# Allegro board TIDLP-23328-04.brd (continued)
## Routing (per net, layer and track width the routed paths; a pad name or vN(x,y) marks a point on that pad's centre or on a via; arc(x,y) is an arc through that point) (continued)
HUM_DRDYZ: length 27.4
  TOP w0.099: v1(57.78,36.83) 57.84,36.88 57.84,37.43 U6.D2 59.06,37.68 R18.1
  LY4-SIG w0.102: v1(44.47,31.01) 45.34,31.88 45.34,35.56 46.99,37.21 46.99,37.72 v1(47.12,37.85)
  LY8-SIG w0.102: v1(47.12,37.85) 48.26,38.99 53.21,38.99 55.37,36.83 v1(57.78,36.83)
  BOTTOM w0.099: U1.A8 40.64,29.52 41.05,29.93 41.05,30.84 41.52,31.31 44.16,31.31 v1(44.47,31.01)
HUM_SCL: length 25
  TOP w0.099: R20.1 57.74,41.61 57.28,41.15 v1(57.28,40.26) 57.09,40.07 U6.A1
  LY3-SIG w0.102: v2(45.27,27.84) 45.87,27.84 48.9,30.86 48.9,31.37 49.91,32.38 50.29,32.38 51.69,33.78 54.1,33.78 57.28,36.96 v1(57.28,40.26)
  BOTTOM w0.099: U1.F2 43.99,27.12 44.73,27.12 45.27,27.65 v2(45.27,27.84)
HUM_SDA: length 25.2
  TOP w0.099: U6.A2 58.09,39.57 v1(57.91,39.75) 57.91,40.04 R19.1
  LY3-SIG w0.102: v1(57.91,39.75) 58.17,39.5 58.17,36.58 56.26,34.67 56.26,30.99 55.5,30.23 48.75,30.23 v2(45.76,27.23)
  BOTTOM w0.099: v2(45.76,27.23) 45.41,27.23 45.06,26.89 44.26,26.89 U1.F1
LI-ION_BATTERY: length 6.5
  BOTTOM w0.203: U19.4 14.55,22.4 R56.2
  BOTTOM w0.305: v1(11.84,21.81) 11.93,21.72 R56.2 ; C71.2 11.21,22.67 J6.1
  vias: v1(10.31,21.81) v1(10.69,21.17) v1(11.08,21.81) v1(11.46,21.17) v1(15.75,25.13) v1(16.13,24.49) v1(16.52,25.13) v1(16.9,24.49) v1(17.28,25.13)
MSD_CARD_DET: length 34.9
  TOP w0.099: v1(16.76,20.57) 16.76,21.32 R7.1 15.64,22.44 P1.13
  LY8-SIG w0.102: v2(38.5,30.66) 38.5,29.63 37.87,29.01 35.25,29.01 34.44,29.82 34.01,29.82 33.43,29.24 32.71,29.24 32.31,28.83 32.31,25.6 29.57,22.86 24.13,22.86 23.62,22.35 21.59,22.35 20.83,23.11 18.41,23.11 17.91,22.61 17.91,21.72 v1(16.76,20.57)
  BOTTOM w0.099: v2(38.5,30.66) 38.25,30.41 38.25,29.93 38.26,29.93 38.26,29.63 38.25,29.63 38.25,29.6 38.14,29.49 U1.A13
MSD_CLK: length 49
  TOP w0.099: P1.5 v1(2.73,10.22)
  LY4-SIG w0.102: v1(2.73,10.22) 4.48,11.97 16.96,11.97 19,14.01 28.07,14.01 29.67,15.61 34.3,15.61 35.31,16.63 40.48,16.63 41.78,17.93 41.78,19.43 42.04,19.68 42.04,21.34 41.66,21.72 v2(41.66,22.5)
  BOTTOM w0.099: U1.T7 41.66,22.28 v2(41.66,22.5)
MSD_CSZ: length 42.7
  TOP w0.099: P1.2 4.13,23.05 v1(4.57,22.61)
  LY4-SIG w0.102: v1(4.57,22.61) 5.09,22.09 9.2,22.09 10.63,20.66 15.02,20.66 15.51,21.14 18.1,21.14 18.35,20.9 22.97,20.9 24.24,19.64 34.8,19.64 35.95,18.48 40.78,18.48 41.02,18.72 41.02,19.34 v2(41.43,19.75)
  BOTTOM w0.099: v2(41.43,19.75) 41.64,19.96 U1.W6 ; v1(4.57,22.61) 4.57,23.36 R5.1
MSD_DI: length 44
  TOP w0.099: P1.3 v1(3.43,22.61)
  LY4-SIG w0.102: v2(41.38,18.99) 41.38,18.54 41.05,18.21 35.64,18.21 34.69,19.15 23.81,19.15 22.77,20.19 18.16,20.19 17.65,19.68 16,19.68 15.36,20.33 9.53,20.33 8.75,21.12 4.92,21.12 v1(3.43,22.61)
  BOTTOM w0.099: U1.V6 41.92,20.49 41.92,19.53 v2(41.38,18.99)
MSD_DO: length 47.4
  TOP w0.099: v1(4.45,10.41) 4.13,10.1 P1.7
  LY4-SIG w0.102: v2(42.42,21.7) 42.42,20.85 42.29,20.72 42.29,19.41 42.52,19.18 42.52,18.76 42.19,18.43 42.19,17.62 40.42,15.85 35.54,15.85 34.55,14.86 29.85,14.86 28.45,13.45 21.65,13.45 19.78,11.59 5.62,11.59 v1(4.45,10.41)
  BOTTOM w0.099: U1.U6 42.08,21.7 v2(42.42,21.7)
Net_207: length 1.8
  BOTTOM w0.099: v2(40.14,30.54) 40.14,28.76
Net_215: length 2.1
  BOTTOM w0.099: 43.64,25.26 43.92,25.54 44.93,25.54 45.37,25.1 v2(45.48,25.1)
OSC0: length 7.2
  BOTTOM w0.099: U1.E19 34.61,27.26 34.35,27.52 33.95,27.52 33.4,28.07 33.4,28.21 33.39,28.21 33.39,28.6 33.15,28.84 C87.2 32.02,29.21 30.35,29.21 29.55,28.41 Y2.1
P1P8V: length 8.2
  TOP w0.203: U7.A1 22.89,11.43 v1(22.89,10.92)
  TOP w0.254: J5.12 43.2,39.98 v1(43.05,40.13) ; C24.1 v1(23.63,10.93) ; J5.11 43.2,43.2 v1(42.8,42.8)
  BOTTOM w0.203: v1(35.59,9.27) 35.26,8.94 U12.A1
  BOTTOM w0.254: v1(43.05,40.13) 43.05,40.88 C61.1 ; R43.1 35.08,11.26 v1(34.49,11.26) ; v1(42.8,42.8) 42.8,42.18 C56.1 ; v1(35.59,9.27) 35.18,9.68 C75.2
P1P8V_BT: length 6.6
  TOP w0.203: U7.A2 22.12,11.48 v1(21.82,11.18)
  TOP w0.254: C13.1 14.04,9.47 v1(14.18,9.61) ; v1(21.82,11.18) 21.49,11.18 21.18,11.48 C20.1
  BOTTOM w0.203: C15.1 11.24,18.36 v1(10.43,18.36) 10.18,18.12 U4.2
  BOTTOM w0.254: U5.18 v1(14.18,9.61) ; R11.2 v1(7.51,12.92)
P3P3V: length 83.5
  TOP w0.203: v1(56.48,38.7) 56.5,38.68 U6.B1
  TOP w0.254: R7.2 17.92,21.46 v1(18.54,21.46) ; R2.2 v1(20.17,33.17) ; J5.8 v1(44,40.07) ; C47.1 v1(51.68,31.08) ; C42.1 36.12,23.31 v2(36.13,23.3) ; R23.2 43.43,5.05 v1(43.43,5.71) ; R18.2 v1(60.1,38.58) ; C36.1 38.26,25.6 v2(38,25.34) ; R28.2 57.21,21.39 v1(57.34,21.52) ; v2(38.01,23.49) 38.34,23.81 C35.1 38.76,23.64 v2(38.76,23.18) ; C6.1 v1(48.29,31.11) ; C50.1 v1(38.71,17.71) ; C85.2 43.77,26.89 v2(43.14,26.26) 43.39,26.01 C86.1 ; R32.2 v1(36.58,14.57) ; C48.1 v1(53.2,31.08) ; R45.1 v1(26.47,15.84) ; C38.1 v1(46.96,17.57) ; U13.4 v1(33.61,16.45) ; v2(54.22,27.52) 54.56,27.18 C7.1 ; R22.2 45.21,6.83 v1(45.21,7.24) ; v2(40.22,22.65) 40.06,22.49 40.06,22.05 C41.1 ; C45.1 v1(29.56,32.64) ; v2(55.02,23.52) 54.9,23.64 C4.1 ; C40.1 v1(50.26,17.57) ; R25.2 v1(47.19,29.92) ; C33.1 40.66,25.46 40.66,25.66 v2(41.11,26.11) ; C2.1 52.57,28.27 v2(51.82,27.52) ; R26.2 v1(47.32,26.59) ; v1(38.5,36.19) 39.25,36.19 R35.2 ; C44.1 v1(34.32,17.57) ; C49.1 v1(54.75,31.1) ; C5.1 56.34,27 v2(55.82,27.52) ; v1(52.14,33.08) 52.18,33.13 C55.1 ; v1(40.64,35.56) 40.39,35.81 R36.2 ; R17.2 41.4,36.18 v1(41.4,35.56) ; C34.1 39.83,25.61 40.19,25.96 v2(40.19,26.23) ; C39.1 v1(48.61,17.57) ; R3.2 v1(21.19,33.17) ; C28.1 v1(28.09,0.89) ; C12.1 21.46,9.14 v1(20.7,9.14) ; J5.7 44,42.87 v1(44.2,42.67) ; C37.1 v1(45.31,17.57) ; C46.1 v1(50.15,30.82) ; C3.1 53.14,23.8 v2(53.42,23.52) ; R6.2 v1(5.82,8.51) ; C1.1 v1(48.29,19.95) ; C23.1 v1(56.48,38.7) ; R1.2 v1(23.22,33.17) ; C43.1 v1(32.58,17.57) ; R4.2 v1(16.66,28.73) ; R20.2 v1(60.33,41.61) ; R27.2 v1(58.23,34.73) ; R19.2 v1(60.33,40.59) ; R24.2 41.66,3.28 v1(41.66,3.81) ; P1.4 v1(2.73,24.7) ; C8.1 v1(58.42,26.5)
  BOTTOM w0.203: U1.J10 U1.J9 ; U1.J9 U1.H9 ; U1.J9 U1.J8 ; v2(38,25.34) 38.07,25.34 U1.K12 U1.K11 ; U1.H9 40.14,26.11 40.19,26.15 v2(40.19,26.23) 40.15,26.26 U1.G10 ; U1.H9 40.77,25.76 ; U1.F3 v2(43.14,26.26) ; U1.L10 U1.L11 U1.M11 39.14,23.56 v2(38.76,23.18) ; 40.77,25.76 40.64,25.64 U1.J8 ; 40.77,25.76 v2(41.11,26.11) ; U1.J8 U1.K8 U1.K7 v2(41.14,25.31) 41.1,25.26 U1.J8 ; v2(42.17,26.82) 42.21,26.82 42.26,26.76 U1.F4 ; U1.L12 U1.M12 38.29,23.77 v2(38.01,23.49) ; U1.N16 36.61,23.3 v2(36.13,23.3) 36.14,23.29 U1.P17 ; U1.P10 39.93,22.77 40.02,22.67 40.2,22.67 v2(40.22,22.65) ; C19.1 v1(5.09,18.15) 5.13,18.12 U4.15
  BOTTOM w0.254: C25.1 42.4,13.12 v1(42.95,12.57) 43.87,11.65 J3.1 ; C10.1 2.73,23.93 v1(2.73,24.7) ; v1(44,40.07) 44,40.82 C60.1 ; U9.14 v1(52.14,33.08) ; U5.12 19.9,9.69 20.45,9.14 v1(20.7,9.14) 21.48,9.14 C11.1 ; U2.B3 v2(55.02,23.52) ; R37.2 v1(41.4,35.56) ; v1(28.09,0.89) 28.09,2.66 J4.1 ; C22.1 v1(27.95,37.34) 27.95,37.34 J2.3 ; U2.A9 v2(55.82,29.12) ; C57.1 44.2,42.18 v1(44.2,42.67) ; U2.A7 v2(55.82,27.52) ; R5.2 v1(3.67,24.63) ; U2.C7 v2(54.22,27.52) ; U2.E7 v2(51.82,27.52) ; U2.J9 v2(48.62,29.12) ; U2.D3 v2(53.42,23.52)
  vias: v1(26.04,17.86) v1(26.04,17.14) v1(26.8,17.86) v1(26.8,17.14)
P5P0V: length 4.2
  TOP w0.203: 31.78,11.43 31.76,11.44 U14.B3 ; U14.C3 31.5,10.64 31.75,10.64 31.78,10.67 ; U14.A3 31.75,12.44 31.75,12.45
  BOTTOM w0.254: J2.2 26.95,38.24 v1(26.05,37.34) C21.1
  vias: v1(32.13,13.76) v1(32.13,12.99)
P_LDO_V: length 58.8
  TOP w0.099: R44.1 v1(16.53,27.71) ; v1(45.85,7.75) 46.13,7.75 46.59,8.21 R42.2 ; C72.2 v1(25.34,30.58) 24.92,30.15 24.92,29.08 24.54,28.7 U10.24
  LY3-SIG w0.102: v1(16.53,27.71) 21.72,22.52 21.72,19.91 27.49,14.15 30.3,14.15 31.37,13.08 31.37,11.56 35.94,6.99 35.94,6.1 36.58,5.46 37.72,5.46 38.86,4.32 41.15,4.32 44.58,7.75 v1(45.85,7.75)
  BOTTOM w0.099: v1(25.34,30.58) 24.16,29.4 20.35,29.4 18.66,27.71 v1(16.53,27.71)
PAD_INTZ: length 15.6
  TOP w0.099: U17.2 v1(42.82,32.84) ; J5.29 v1(39.6,41.28)
  LY4-SIG w0.102: v1(42.82,32.84) 42.82,39.16 42.28,39.7 42.28,41.49 41.79,41.97 40.29,41.97 v1(39.6,41.28)
PAD_RSTZ: length 32.5
  TOP w0.099: U15.1 35.05,31.37 v1(34.54,30.86) ; J5.31 39.2,41.7 v1(38.84,41.34)
  LY7-SIG w0.102: v1(38.84,41.34) 37.94,40.44 37.94,39.96 37.33,39.35 26.81,39.35 25.54,38.09 25.54,35.46 26.24,34.77 28.19,34.77 30.4,32.56 30.4,32.05 31.59,30.86 v1(34.54,30.86)
PAD_RSTZ_P3P3V: length 40.3
  TOP w0.099: J5.28 v1(40,38.18)
  LY4-SIG w0.102: v2(36.67,21.45) 36.67,21.1 36.33,20.76 34.57,20.76 33.61,21.72 29.72,21.72 28.07,23.37 28.07,26.04 26.27,27.83 26.27,30.52 25.58,31.21 25.58,32.38 26.21,33.01 v1(26.21,35.54)
  LY7-SIG w0.102: v1(40,38.18) 39.73,38.45 30.63,38.45 28.81,36.64 27.31,36.64 v1(26.21,35.54)
  BOTTOM w0.099: v2(36.67,21.45) 36.68,21.45 36.87,21.27 U1.U15
PCLK: length 37.4
  TOP w0.099: J5.45 36.4,42.39 v1(36.65,42.14)
  LY4-SIG w0.102: v2(41.69,23.33) 41.69,23.69 41.56,23.82 41,23.82 40.76,24.06 40.76,26.34 40.89,26.47 41.25,26.47 41.38,26.6 41.38,27.02 41.21,27.2 41.21,27.7 41.56,28.05 41.56,29.42 41.28,29.7 41.28,30.75 41.61,31.08 41.61,33.62 40.86,34.37 39.57,34.37 39.36,34.59 39.36,35.28 38.97,35.67 38.33,35.67 37.64,36.36 37.64,37.33 37.95,37.65 37.95,38.01 37.85,38.11 36.68,38.11 36.56,38.23 36.56,38.37 36.69,38.51 38.44,38.51 38.56,38.63 38.56,38.78 38.42,38.92 36.65,38.92 36.55,39.02 36.55,39.19 36.65,39.3 37.71,39.3 37.84,39.43 37.84,39.57 37.68,39.74 36.65,39.74 36.39,40 36.39,40.92 36.03,41.28 36.03,41.6 35.39,42.24 35.39,42.56 35.06,42.89 35.06,43.27 35.37,43.58 36.01,43.58 36.3,43.29 36.3,42.49 v1(36.65,42.14)
  BOTTOM w0.099: U1.N5 41.88,23.27 41.84,23.31 41.72,23.31 v2(41.69,23.33)
PDATA_00: length 39.7
  TOP w0.099: J5.51 35.2,41.86 35.38,41.68 35.39,41.68 v1(35.41,41.66)
  LY3-SIG w0.102: v2(38.11,26.83) 38.11,26.84 38.23,26.95 38.23,27.5 37.08,28.65 36.3,28.65 35.57,29.38 35.57,29.86 35.18,30.25 34.58,30.25 34.41,30.41 33.48,30.41 32.94,30.95 32.44,30.95 32.31,31.08 32.31,31.41 31.56,32.16 31.02,32.16 30.45,32.74 30.45,33.11 29.81,33.75 29.81,34.02 29.91,34.12 30.11,34.12 31.22,33.02 31.29,33.02 31.52,32.8 31.52,32.72 32.72,31.51 32.93,31.51 33.04,31.61 33.04,31.89 30.4,34.53 30.4,38.42 29.73,39.09 29.73,40.16 29.94,40.36 29.94,40.81 30.31,41.18 30.31,42.45 31.2,43.34 32.14,43.34 32.39,43.09 32.39,42.2 32.62,41.98 34.08,41.98 34.23,41.83 34.84,41.83 35.01,41.66 v1(35.41,41.66)
  BOTTOM w0.099: v2(38.11,26.83) 38.47,27.19 38.47,27.44 U1.D13
PDATA_01: length 39.6
  TOP w0.099: J5.52 v1(35.2,40.8)
  LY3-SIG w0.102: v1(35.2,40.8) 35.8,41.4 35.8,41.82 35.5,42.13 34.49,42.13 34.28,42.34 34.28,42.97 33.59,43.65 30.4,43.65 29.49,42.74 29.49,41.83 29.26,41.6 27.71,41.6 27.17,41.06 27.17,38.74 28.43,37.48 28.43,36.12 25.88,33.56 25.88,30.03 25.91,30 25.91,29.69 25.88,29.66 25.88,28.83 27.88,26.83 31.89,26.83 32.78,27.71 v2(33.1,27.71)
  BOTTOM w0.099: v2(33.1,27.71) 33.1,27.66 33.58,27.18 34.09,27.18 34.4,26.87 35.25,26.87 U1.E18
PDATA_02: length 37.5
  TOP w0.099: J5.53 v1(34.8,42.52)
  LY4-SIG w0.102: v1(34.8,42.52) 33.57,43.75 25.74,43.75 24.14,42.15 24.14,39.89 25.49,38.55 25.49,36.72 25.99,36.22 27.28,36.22 27.7,35.79 27.7,32.84 28.8,31.75 28.8,28.01 29.66,27.14 33.11,27.14 33.49,26.76 v2(33.86,26.76)
  BOTTOM w0.099: v2(33.86,26.76) 34.07,26.56 35.43,26.56 U1.F18
PDATA_03: length 37.8
  TOP w0.099: v1(34.59,41.36) 34.8,41.15 J5.54
  LY4-SIG w0.102: v2(42.65,22.27) 42.9,22.53 43.5,22.53 43.6,22.63 43.6,23.54 43.36,23.79 42.76,23.79 42.68,23.71 42.68,23.56 42.76,23.49 42.76,23.25 42.68,23.17 42.04,23.17 41.82,22.95 41.55,22.95 41.34,23.16 41.34,23.38 41.15,23.57 40.9,23.57 40.51,23.97 40.51,26.05 40.54,26.08 40.54,26.91 40.35,27.09 40.35,27.42 40.82,27.89 40.82,28.41 40.96,28.55 40.96,30.94 41.29,31.26 41.29,33.47 40.78,33.98 38.81,33.98 38.25,34.54 38.25,35.19 37.25,36.2 37.25,36.68 36.72,37.21 36.4,37.21 36.21,37.4 36.21,39.65 36.11,39.75 35.9,39.75 35.8,39.65 35.8,36.8 35.67,36.67 35.53,36.67 35.39,36.8 35.39,39.67 35.21,39.85 35.21,40.22 34.8,40.63 34.8,41.16 v1(34.59,41.36)
  BOTTOM w0.099: U1.P3 v2(42.65,22.27)
PDATA_04: length 37.7
  TOP w0.099: J5.55 34.4,41.98 33.99,41.57 v1(33.78,41.57)
  LY3-SIG w0.102: v2(45.42,22.77) 44.44,22.77 43.62,23.58 43.62,24.82 43.82,25.01 43.82,28.32 43.17,28.96 42.01,28.96 41.27,29.7 41.27,32.42 41,32.69 39.55,32.69 37.72,34.52 37.72,35.24 37.14,35.81 36.3,35.81 35.09,37.02 35.09,37.42 35.25,37.58 36.04,37.58 36.19,37.73 36.19,37.88 36.07,38 35.38,38 35.27,38.11 35.27,38.3 35.46,38.49 36.81,38.49 36.9,38.58 36.9,38.82 36.82,38.9 35.34,38.9 35.21,39.04 35.21,39.2 35.32,39.31 36.27,39.31 36.38,39.42 36.38,39.56 36.23,39.71 35.41,39.71 34.85,40.27 34.85,40.52 34.39,40.98 34.39,41 34.16,41.23 34.14,41.23 33.8,41.57 v1(33.78,41.57)
  BOTTOM w0.099: v2(45.42,22.77) 45.08,22.77 45,22.68 44.54,22.68 44.46,22.77 U1.P2
PDATA_05: length 37.6
  TOP w0.099: J5.56 v1(34.4,40.15)
  LY4-SIG w0.102: v1(34.4,40.15) 34.4,38.28 34.46,38.22 34.46,34.65 34.95,34.16 36.48,34.16 36.64,34 36.64,33.86 36.52,33.74 35.62,33.74 35.48,33.6 35.48,33.45 35.97,32.95 37.24,32.95 38.3,31.9 38.3,31.36 38.85,30.81 38.85,30.46 38.32,29.93 38.32,29.42 39.6,28.15 39.6,23.51 39.84,23.26 39.84,21.55 39.68,21.39 39.68,21.01 39.58,20.91 37.23,20.91 36.95,20.63 36.95,20.38 37.17,20.16 37.37,20.16 37.47,20.27 37.47,20.46 37.57,20.56 37.77,20.56 37.88,20.46 37.88,20.27 37.98,20.16 38.18,20.16 38.28,20.27 38.28,20.46 38.38,20.56 38.59,20.56 38.73,20.42 38.73,19.51 38.84,19.41 38.99,19.41 39.1,19.51 39.1,20.46 39.2,20.56 39.4,20.56 39.5,20.46 39.5,20.27 39.6,20.16 40.07,20.16 40.31,20.4 40.31,20.4 40.52,20.61 40.52,20.61 v2(41.17,21.27)
  BOTTOM w0.099: U1.U8 v2(41.17,21.27)
PDATA_06: length 38.4
  TOP w0.099: J5.57 34,42.58 33.88,42.46 v1(33.88,42.44)
  LY4-SIG w0.102: v2(40.66,20.26) 41.06,20.66 41.37,20.66 41.67,20.95 41.67,21.33 40.59,22.4 40.59,23.45 40.07,23.96 40.07,25.67 39.85,25.89 39.85,26.06 39.8,26.11 39.8,28.36 39.62,28.54 39.62,29.28 39.91,29.57 39.91,30.1 39.74,30.27 39.74,30.93 39.59,31.08 39.07,31.08 38.85,31.3 38.85,31.6 39,31.74 39.5,31.74 39.62,31.86 39.62,32.07 39.47,32.22 38.61,32.22 38.45,32.37 38.45,32.64 38.65,32.84 39.29,32.84 39.41,32.97 39.41,33.2 39.27,33.35 37.27,33.35 37.06,33.55 37.06,33.91 37.32,34.17 37.32,34.51 37.42,34.61 37.68,34.61 37.84,34.78 37.84,34.99 37.55,35.28 37.41,35.28 37.31,35.38 37.31,35.63 37.21,35.73 37.01,35.73 36.9,35.63 36.9,35.38 36.8,35.28 36.6,35.28 36.5,35.38 36.5,36.07 36.37,36.19 36.19,36.19 36.09,36.09 36.09,35.38 35.99,35.28 35.79,35.28 35.68,35.38 35.68,36.07 35.56,36.19 35.38,36.19 35.28,36.09 35.28,35.38 35.18,35.28 34.97,35.28 34.87,35.38 34.87,40.24 34.54,40.57 34.54,40.86 34.25,41.15 34.25,41.15 34.2,41.2 34.2,41.86 33.87,42.19 33.87,42.43 v1(33.88,42.44)
  BOTTOM w0.099: U1.V8 40.66,20.74 v2(40.66,20.26)
PDATA_07: length 38.5
  TOP w0.099: J5.58 v1(34,40.83)
  LY3-SIG w0.102: v1(34,40.83) 34,39.94 34.88,39.06 34.88,37.93 34.45,37.5 34.45,36.91 35.97,35.4 36.63,35.4 37.3,34.73 37.3,34.48 40.39,31.39 40.39,31.34 40.71,31.01 40.71,30.99 40.89,30.81 40.89,29.67 42.21,28.35 42.21,28.13 42.52,27.82 42.52,27.03 42.68,26.87 42.68,26.11 42.97,25.82 43.21,25.82 43.56,25.47 43.56,25.13 43.36,24.93 43.36,24.12 43.36,24.03 43.12,23.79 42.82,23.79 42.45,23.41 42.45,23.14 43.38,22.2 43.96,22.2 44.08,22.08 44.08,21.73 43.83,21.48 42.74,21.48 42.53,21.27 42.53,20.98 42.81,20.7 43.7,20.7 44.6,21.59 44.89,21.59 45.01,21.47 45.01,21.13 44.05,20.17 42.57,20.17 42.25,20.49 41.42,20.49 40.82,19.89 40.8,19.89 v2(40.66,19.75)
  BOTTOM w0.099: U1.W9 40.15,20.27 v2(40.66,19.75)
PDATA_08: length 38.2
  TOP w0.099: J5.61 33.2,43.22 33.06,43.08 33.06,42.76 33.2,42.62 33.2,41.79 v1(32.9,41.49)
  LY4-SIG w0.102: v1(32.9,41.49) 32.93,41.47 32.93,40.74 33.2,40.46 33.2,39.48 33.31,39.38 33.87,39.38 34,39.25 34,39.03 33.89,38.92 33.33,38.92 33.2,38.79 33.2,38.56 33.31,38.44 33.98,38.44 34.1,38.33 34.1,38.11 33.98,37.99 32.67,37.99 32.52,37.84 32.52,37.67 32.62,37.57 33.32,37.57 33.42,37.47 33.42,37.29 33.28,37.15 32.51,37.15 32.41,37.04 32.41,36.85 32.51,36.74 33.93,36.74 34.03,36.64 34.03,36.44 33.91,36.32 32.54,36.32 32.4,36.18 32.4,36.04 32.55,35.89 33.55,35.89 33.96,35.47 33.96,34.81 33.84,34.69 33.59,34.69 33.44,34.84 33.44,35.24 33.21,35.47 31.67,35.47 31.57,35.37 31.57,35.2 31.67,35.1 32.41,35.1 32.52,35 32.52,34.82 32.42,34.73 32.14,34.73 32.02,34.6 32.02,34.42 32.15,34.29 34.33,34.29 34.43,34.19 34.43,33.94 34.32,33.84 32.65,33.84 32.57,33.75 32.57,33.48 32.69,33.35 35.01,33.35 35.86,32.5 37,32.5 37.9,31.6 v2(37.9,30.54)
  BOTTOM w0.099: U1.B14 37.36,29.04 37.36,30 v2(37.9,30.54)
PDATA_09: length 39
  TOP w0.099: J5.62 33.2,40.83 v1(33.37,41.01)
  LY4-SIG w0.102: v2(37.11,27.12) 36.3,27.12 35.71,27.71 35.71,29.93 35.51,30.14 34.1,30.14 34,30.24 34,31.14 33.89,31.24 33.69,31.24 33.59,31.14 33.59,30.23 33.49,30.13 33.28,30.13 33.18,30.23 33.18,31.14 33.08,31.24 32.88,31.24 32.78,31.14 32.78,30.23 32.67,30.13 32.47,30.13 32.37,30.23 32.37,31.14 32.27,31.24 32.06,31.24 31.96,31.14 31.96,30.23 31.86,30.13 31.66,30.13 31.56,30.23 31.56,31.14 31.46,31.24 31.25,31.24 31.15,31.14 31.15,30.23 31.05,30.13 30.85,30.13 30.57,30.41 30.57,31.49 30.89,31.81 31.33,31.81 31.54,32.02 31.54,32.98 31.23,33.29 31,33.29 30.16,34.13 29.64,34.13 29.4,34.37 29.4,36.2 29.91,36.7 29.91,37.85 29.51,38.24 29.13,38.24 28.87,38.5 28.87,39.21 29.37,39.71 29.74,39.71 30,39.46 30.4,39.46 30.77,39.82 30.77,40.54 31.65,41.42 31.65,41.77 31.8,41.92 33.18,41.92 33.37,41.73 v1(33.37,41.01)
  BOTTOM w0.099: v2(37.11,27.12) 36.49,27.12 U1.F17
PDATA_10: length 38.4
  TOP w0.099: J5.63 v1(32.8,42.44)
  LY4-SIG w0.102: v2(39.22,22.69) 38.78,22.25 37.82,22.25 37.34,22.73 35.99,22.73 35.27,23.45 35.27,26.16 33.89,27.54 33.44,27.54 33.26,27.36 32.73,27.36 32.55,27.54 29.91,27.54 29.3,28.15 29.3,31.99 28.23,33.06 28.23,36.09 27.44,36.88 27.44,37.72 26.58,38.58 26.58,41.89 27.28,42.59 29.32,42.59 30.11,43.38 31.86,43.38 v1(32.8,42.44)
  BOTTOM w0.099: v2(39.22,22.69) 39.22,22.69 U1.R10
PDATA_11: length 37.8
  TOP w0.099: J5.64 v1(32.8,40.18)
  LY3-SIG w0.102: v1(32.8,40.18) 33.13,40.18 33.24,40.07 33.24,39.79 33.14,39.69 32.46,39.69 32.38,39.61 32.38,39.49 32.54,39.33 34.03,39.33 34.14,39.22 34.14,39.05 34.04,38.95 32.47,38.95 32.35,38.84 32.35,38.64 32.45,38.54 34.35,38.54 34.5,38.39 34.5,38.25 34.37,38.13 32.6,38.13 32.5,38.02 32.5,37.88 32.61,37.77 33.23,37.77 33.41,37.59 33.41,36.95 33.75,36.61 34.15,36.61 35.68,35.08 35.68,34.29 36,33.98 36.93,33.98 39.76,31.15 39.76,30.25 39.95,30.06 39.95,29.7 40.34,29.3 40.34,29.16 40.23,29.05 39.9,29.05 39.5,29.44 39.36,29.44 39.26,29.34 39.26,29.14 39.72,28.67 40.39,28.67 40.62,28.44 40.62,27.68 40.35,27.42 40.35,27.41 40.35,27.12 40.35,27.11 40.35,27.09 40.58,26.87 40.58,26.03 40.77,25.84 40.77,23.71 40.58,23.52 40.58,23.1 40.58,23.1 40.58,22.53 40.83,22.28 41.17,22.28 41.28,22.16 41.28,21.94 41.12,21.77 40.76,21.77 40.48,22.05 40.26,22.05 40.16,21.95 v2(40.16,21.27)
  BOTTOM w0.099: v2(40.16,21.27) 40.14,21.26 U1.V9
PDATA_12: length 39.1
  TOP w0.099: J5.65 32.4,41.96 32.12,41.68 32.12,41.42 v1(32.11,41.41)
  LY4-SIG w0.102: v2(38.51,22.65) 38.36,22.8 38.36,23.3 38.79,23.73 38.79,25.8 39.19,26.2 39.19,27.21 38.97,27.43 38.17,27.43 36.76,28.84 36.76,30.85 36.55,31.06 35.55,31.06 35.3,31.32 35.3,31.87 35.19,31.97 34.99,31.97 34.89,31.87 34.89,31.48 34.76,31.35 34.58,31.35 34.48,31.45 34.48,32.47 34.38,32.57 34.2,32.57 34.08,32.45 34.08,31.73 33.98,31.63 33.77,31.63 33.67,31.73 33.67,32.47 33.57,32.57 33.38,32.57 33.26,32.45 33.26,31.73 33.16,31.63 32.96,31.63 32.86,31.73 32.86,32.47 32.76,32.57 32.57,32.57 32.45,32.45 32.45,31.73 32.35,31.63 32.15,31.63 31.89,31.89 31.89,33.36 31.55,33.7 31.15,33.7 30.41,34.44 30.41,35.01 29.95,35.47 29.95,35.86 30.46,36.38 30.46,37.85 29.7,38.61 29.41,38.61 29.26,38.76 29.26,39.1 29.44,39.28 29.72,39.28 29.93,39.06 30.46,39.06 31.07,39.67 31.84,39.67 32.14,39.97 32.14,40.93 32.11,40.96 v1(32.11,41.41)
  BOTTOM w0.099: v2(38.51,22.65) 38.51,22.14 U1.T13
PDATA_13: length 38.8
  TOP w0.099: J5.66 32.4,40.37 32.53,40.5 v1(32.53,40.93)
  LY4-SIG w0.102: v1(32.53,40.93) 32.53,40.47 32.41,40.34 32.41,39.95 32.84,39.52 32.84,39.31 32.73,39.19 30.98,39.19 30.82,39.03 30.82,38.83 30.94,38.71 32.64,38.71 32.74,38.6 32.74,38.41 32.64,38.31 30.76,38.31 30.66,38.2 30.66,38.01 30.77,37.9 31.48,37.9 31.58,37.8 31.58,37.6 31.48,37.49 31.05,37.49 30.94,37.39 30.94,37.19 31.05,37.09 31.62,37.09 31.73,36.97 31.73,36.78 31.63,36.68 31.05,36.68 30.94,36.58 30.94,36.38 31.05,36.27 31.86,36.27 31.96,36.17 31.96,35.98 31.85,35.87 30.56,35.87 30.38,35.69 30.38,35.51 30.56,35.33 30.95,35.33 31.65,34.64 31.65,34.26 32.21,33.7 32.21,33.3 32.56,32.95 34.76,32.95 36.27,31.44 36.77,31.44 37.51,30.7 37.51,29.51 38.51,28.52 38.51,28.19 39.39,27.3 39.39,25.95 39.17,25.73 39.17,23.36 39.58,22.94 39.58,21.72 v2(39.13,21.27)
  BOTTOM w0.099: U1.U10 v2(39.13,21.27)
PDATA_14: length 37.5
  TOP w0.099: J5.67 v1(32,42.45)
  LY4-SIG w0.102: v1(32,42.45) 31.82,42.45 31.35,41.99 30.92,41.99 30.71,42.2 30.46,42.2 30.1,41.84 29.57,41.84 29.22,41.5 28.76,41.5 28.62,41.64 28.62,41.91 28.38,42.15 27.6,42.15 27.1,41.65 27.1,38.84 28.45,37.49 28.45,36.82 28.71,36.56 28.71,33.49 28.98,33.22 29.66,33.22 30.14,32.75 30.14,32.34 29.83,32.04 29.83,29.09 30.21,28.71 30.41,28.71 30.51,28.82 30.51,29.11 30.61,29.21 30.82,29.21 30.92,29.11 30.92,28.82 31.02,28.71 31.22,28.71 31.32,28.82 31.32,29.11 31.43,29.21 31.63,29.21 31.73,29.11 31.73,28.82 31.83,28.71 32.04,28.71 32.14,28.82 32.14,29.11 32.24,29.21 32.44,29.21 32.54,29.11 32.54,28.97 32.65,28.87 33.1,28.87 33.79,28.18 34.13,28.18 34.37,28.41 34.72,28.41 35,28.13 35,27.03 35.62,26.42 35.62,24.09 35.96,23.75 36.33,23.75 36.86,23.22 37.41,23.22 v2(37.7,22.93)
  BOTTOM w0.099: v2(37.7,22.93) 38.14,22.49 U1.R13
PDATA_15: length 37.3
  TOP w0.099: v1(31.75,40.76) 32.02,40.49 32.02,39.2 J5.68
  LY3-SIG w0.102: v1(31.75,40.76) 31.8,40.71 31.8,40.54 32.04,40.3 32.04,37.94 32.84,37.14 32.84,36.65 33.41,36.08 33.9,36.08 34.68,35.3 34.68,34.06 35.18,33.56 36.95,33.56 37.18,33.32 37.18,32.32 37.7,31.8 38.61,31.8 38.87,31.54 38.87,30.53 38.55,30.21 38.55,29.36 39.48,28.44 39.48,26.12 39.72,25.87 40.28,25.87 40.35,25.8 40.35,25.65 40.21,25.51 39.19,25.51 39.09,25.41 39.09,25.25 39.23,25.11 40.4,25.11 40.5,25.01 40.5,24.83 40.4,24.73 39.22,24.73 39.12,24.63 39.12,24.49 39.26,24.35 40.38,24.35 40.49,24.24 40.49,24.03 40.39,23.92 39.22,23.92 39.12,23.82 39.12,23.68 39.28,23.52 39.63,23.52 39.8,23.35 39.8,20.85 39.52,20.57 39.52,20.11 39.19,19.78 39.19,19.57 39.38,19.38 39.53,19.38 v2(39.9,19.75)
  BOTTOM w0.099: v2(39.9,19.75) 39.64,20.01 U1.W10
PDATA_16: length 37.9
  TOP w0.099: J5.71 v1(31.2,42.44)
  LY3-SIG w0.102: v1(31.2,42.44) 31.2,42.27 31.47,42 31.47,41.27 31.16,40.96 31.16,39.57 31.57,39.17 31.57,36.1 31.66,36.01 31.84,36.01 31.95,36.11 31.95,36.75 32.05,36.85 32.2,36.85 32.31,36.74 32.31,35.88 32.11,35.68 32.11,34.54 32.21,34.44 32.34,34.44 32.49,34.59 32.49,35.52 32.6,35.62 33.86,35.62 34.13,35.35 34.13,35.2 33.99,35.06 33.85,35.06 33.68,35.23 33.49,35.23 33.38,35.12 33.38,34.86 33.55,34.69 34.22,34.69 34.32,34.59 34.32,34.36 34.22,34.26 32.91,34.26 32.79,34.13 32.79,33.99 32.95,33.83 34.33,33.83 34.45,33.71 34.45,33.57 34.3,33.42 33.69,33.42 33.6,33.33 33.6,33.18 33.8,32.98 36.6,32.98 36.72,32.86 36.72,32.65 36.62,32.55 34.4,32.55 34.25,32.39 34.25,32.24 34.35,32.14 36.37,32.14 36.48,32.02 36.48,31.88 36.37,31.76 35.88,31.76 35.8,31.69 35.8,31.48 35.97,31.31 38.28,31.31 38.41,31.18 38.41,31.08 38.28,30.95 37.6,30.95 37.51,30.85 37.51,30.18 v2(37.9,29.78)
  BOTTOM w0.099: v2(37.9,29.78) 37.64,29.52 U1.A14
PDATA_17: length 37.8
  TOP w0.099: J5.72 31.2,40.55 31.19,40.56 31.19,40.58 31.19,40.91 31.2,40.92 31.2,41.22 31.04,41.38 v1(31.04,41.51)
  LY4-SIG w0.102: v1(31.04,41.51) 30.58,41.51 30.17,41.1 30.17,41.1 29.95,40.88 29.94,40.88 29.94,40.87 29.6,40.87 29.24,41.22 28.5,41.22 28.31,41.42 28.31,41.65 28.17,41.79 27.8,41.79 27.54,41.53 27.54,40.81 27.64,40.7 28.55,40.7 28.65,40.6 28.65,40.4 28.55,40.3 27.64,40.3 27.54,40.2 27.54,39.99 27.64,39.89 28.55,39.89 28.65,39.79 28.65,39.59 28.55,39.48 27.64,39.48 27.54,39.38 27.54,39.02 27.69,38.87 27.83,38.87 28,39.05 28.15,39.05 28.29,38.9 28.29,38.76 28.12,38.59 28.12,38.44 28.67,37.89 29.25,37.89 29.45,37.69 29.45,37.01 29.05,36.61 29.05,33.91 29.24,33.72 29.92,33.72 30.51,33.13 30.51,32.11 30.23,31.83 30.23,29.96 30.54,29.65 32.5,29.65 32.9,29.25 33.39,29.25 33.79,29.65 34.08,29.65 34.31,29.42 34.84,29.42 35.34,28.93 35.34,27.56 36.55,26.35 37.92,26.35 38,26.43 38.32,26.43 38.47,26.58 38.47,26.72 v2(38.82,27.08)
  BOTTOM w0.099: v2(38.82,27.08) 38.86,27.11 38.86,27.55 U1.D12
PDATA_18: length 38.1
  TOP w0.099: v1(29.79,41.26) 29.83,41.29 30.12,41.29 30.8,41.98 J5.73
  LY3-SIG w0.102: v2(36.49,27.61) 35.82,27.61 35.49,27.93 35.49,28.66 34.98,29.17 34.77,29.38 34.77,29.38 34.22,29.93 33.52,29.93 33.39,30.07 33.06,30.07 32.71,29.73 31.37,29.73 31.09,30 31.09,30.46 30.58,30.97 30.03,30.97 29.71,31.28 29.03,31.28 28.63,31.69 28.63,33.22 28.33,33.52 28.33,33.84 28.48,34 28.73,34 29.06,33.67 29.06,32.04 29.37,31.73 29.97,31.73 30.27,31.43 30.85,31.43 31.47,30.81 31.47,30.23 31.63,30.07 32.74,30.07 32.89,30.23 32.89,30.37 32.73,30.53 32.04,30.53 31.95,30.62 31.95,31 31.13,31.82 30.67,31.82 30.28,32.2 30.12,32.2 29.98,32.35 29.98,32.94 29.49,33.42 29.49,33.83 29.12,34.2 29.12,34.64 29.99,35.51 29.99,38.2 29.49,38.71 29.49,40.29 29.54,40.35 29.54,41.01 v1(29.79,41.26)
  BOTTOM w0.099: U1.E17 v2(36.49,27.61)
PDATA_19: length 39.1
  TOP w0.099: v1(30.4,40.7) 30.51,40.59 30.57,40.59 30.8,40.36 J5.74
  LY3-SIG w0.102: v2(39.9,18.99) 39.9,18.76 39.42,18.28 39.42,16.22 39.04,15.83 38.27,15.83 38.1,16 38.1,17.83 38.79,18.51 38.79,18.84 38.78,18.84 38.78,19.8 39.19,20.2 39.19,20.7 39.5,21.01 39.5,22.47 39.57,22.54 39.57,22.92 38.83,23.66 38.83,25.82 39.2,26.18 39.2,27.36 38.76,27.8 38.76,28.5 37.95,29.31 37.48,29.31 36.78,30 36.78,30.76 36.53,31.01 35.83,31.01 35.17,31.67 34.26,31.67 33.94,31.99 33.94,32.27 31.74,34.47 31.74,35.36 31.22,35.88 31.22,38.82 30.83,39.21 30.83,40.54 30.67,40.7 30.49,40.7 30.48,40.7 v1(30.4,40.7)
  BOTTOM w0.099: U1.V10 39.36,20.49 39.36,19.53 v2(39.9,18.99)
PDATA_20: length 39.6
  TOP w0.099: J5.75 30.4,42.05 30.16,41.81 29.52,41.81 29.33,42 v1(29.09,42)
  LY3-SIG w0.102: v2(38.13,21.27) 37.64,20.78 35.68,20.78 35.19,21.26 35.19,24.92 34.22,25.89 34.22,26.17 33.99,26.4 33.66,26.4 33.51,26.25 27.59,26.25 24.8,29.04 24.8,33.57 26.67,35.43 26.67,35.44 26.89,35.66 26.9,35.66 27.39,36.16 27.39,37.55 26.54,38.41 26.54,41.2 27.33,42 v1(29.09,42)
  BOTTOM w0.099: U1.U12 v2(38.13,21.27)
PDATA_21: length 37.4
  TOP w0.099: J5.76 30.4,39.93 v1(30.24,40.09)
  LY3-SIG w0.102: v2(39.11,21.94) 38.77,21.6 38.77,20.33 38.62,20.18 38.1,20.18 38,20.08 38,18.51 37.59,18.11 37.09,18.11 36.85,18.35 36.85,18.49 36.99,18.64 37.51,18.64 37.62,18.76 37.62,19.03 37.53,19.13 36.99,19.13 36.85,19.27 36.85,19.54 36.95,19.64 37.37,19.64 37.55,19.82 37.55,20.25 37.97,20.67 38.31,20.67 38.49,20.85 38.49,21.81 38.15,22.15 38.15,23.1 38.5,23.45 38.5,26.18 38.48,26.2 38.48,26.5 38.5,26.52 38.5,26.9 38.47,26.93 38.47,27.23 38.5,27.26 38.5,28.39 37.95,28.95 36.63,28.95 36.02,29.55 36.02,29.7 35.18,30.55 35.18,31.11 34.96,31.34 34.35,31.34 34.16,31.15 34.16,30.99 33.99,30.82 33.67,30.82 33.49,31 33.49,32.08 31.32,34.25 31.32,35.13 30.87,35.59 30.87,38.59 30.24,39.21 v1(30.24,40.09)
  BOTTOM w0.099: U1.T12 38.81,21.94 v2(39.11,21.94)
PDATA_22: length 38
  TOP w0.099: v1(29.9,42.29) 29.9,42.57 30,42.68 J5.77
  LY3-SIG w0.102: v1(29.9,42.29) 29.9,42.06 29.72,41.88 29.72,41.74 29.35,41.38 29.14,41.38 27.88,40.12 27.88,39.17 29.38,37.67 29.38,36.45 27.05,34.13 27.05,33.65 26.95,33.55 26.38,33.55 26.28,33.45 26.28,33.25 26.38,33.14 27.47,33.14 27.57,33.04 27.57,32.85 27.46,32.74 26.38,32.74 26.28,32.64 26.28,32.43 26.38,32.33 27.47,32.33 27.57,32.23 27.57,32.04 27.46,31.92 26.38,31.92 26.28,31.82 26.28,31.62 26.38,31.52 26.95,31.52 27.05,31.42 27.05,30.84 26.39,30.18 26.39,28.97 28.26,27.1 28.73,27.1 28.91,27.27 31.03,27.27 31.34,27.58 31.34,28.52 31.62,28.8 33.14,28.8 33.39,28.55 33.39,28.31 33.72,27.98 33.96,27.98 34.42,27.52 34.75,27.52 35.74,26.53 35.74,26.12 36.14,25.72 v2(36.14,25.33)
  BOTTOM w0.099: U1.H17 v2(36.14,25.33)
PDATA_23: length 39.2
  TOP w0.099: J5.78 30,39.77 29.74,40.03 29.74,40.14 v1(29.14,40.74)
  LY3-SIG w0.102: v1(29.14,40.74) 28.37,39.96 28.37,39.27 29.66,37.98 29.66,35.87 27.7,33.91 27.7,33.55 28.12,33.13 28.12,31.94 27.69,31.51 27.69,31.14 28.1,30.73 29.23,30.73 29.48,30.48 30.32,30.48 30.63,30.17 30.63,29.33 30.5,29.2 30.3,29.2 30.13,29.37 30.13,29.95 30.02,30.06 29.79,30.06 29.67,29.94 29.67,28.17 29.54,28.03 29.32,28.03 29.17,28.18 29.17,30.11 29.02,30.27 28.76,30.27 28.6,30.11 28.6,28.14 29.1,27.64 29.95,27.64 30.29,27.97 30.29,28.49 30.57,28.77 30.98,28.77 31.38,29.17 33.34,29.17 33.6,28.91 33.6,28.39 33.81,28.19 34.1,28.19 34.33,28.42 34.71,28.42 35.05,28.08 35.05,27.8 36.12,26.73 v2(37.59,26.73)
  BOTTOM w0.099: v2(37.59,26.73) 36.67,26.73 U1.F16
PROJ_ON: length 31.1
  TOP w0.099: U15.2 35.7,34.21 35.92,34.43 36.67,34.43 v1(36.87,34.62) 36.87,35.79 36.04,36.61 36.04,36.8 36.38,37.14 37.09,37.14 37.51,37.56 v1(38.33,37.56) 38.33,37.61 38.51,37.79 38.51,38.06 38.4,38.17 J5.36 ; v2(41.63,24.3) 41.64,24.29 41.78,24.29 42.22,24.74 42.54,24.74 42.59,24.69 43.18,24.69 43.95,23.92 45.86,23.92 R31.2 47.17,24.56 v1(47.24,24.64)
  LY3-SIG w0.102: v2(41.63,24.3) 41.63,24.5 42.49,25.36 42.49,25.72 42.09,26.12 42.09,26.37 41.68,26.78 41.61,26.78 41.21,27.17 41.21,27.57 41.58,27.94 41.58,28.57 40.51,29.64 40.51,30.78 36.87,34.42 v1(36.87,34.62)
  BOTTOM w0.099: v2(41.63,24.3) 41.63,24.3 41.67,24.3 U1.K5
PS_EN: length 3.3
  TOP w0.099: U18.4 47.02,34.07 47.39,34.43 47.39,35.84 R52.2
SCLK: length 2.2
  BOTTOM w0.099: R15.1 30.95,36.63 J2.6
SCLKP: length 15.2
  LY7-SIG w0.102: v2(41.64,30.54) 41.09,31.09 40.59,31.09 38.06,33.62 32.11,33.62 v1(30.93,34.8)
  BOTTOM w0.099: R15.2 v1(30.93,34.8) ; v2(41.64,30.54) 41.43,30.33 41.43,28.98 U1.B6
SDR_AD00: length 32.6
  LY3-SIG w0.102: v2(49.42,27.52) 49.78,27.89 49.78,28.44 50.06,28.72 52.17,28.72 52.95,27.94 55.43,27.94 v2(55.82,28.32)
  LY7-SIG w0.102: v2(49.42,27.52) 50.04,26.9 51.69,26.9 51.98,26.61 51.98,25.02 51.05,24.09 48.44,24.09 47.91,23.57 47.91,20.98 48.81,20.08 48.81,19.43 48.14,18.75 47.58,18.75 47.2,19.13 46.19,19.13 45.88,19.44 45.88,20.48 45.53,20.83 44.25,20.83 43.39,21.69 43.39,22.31 42.93,22.77 v2(42.13,22.77)
  BOTTOM w0.099: U1.P4 v2(42.13,22.77) ; U2.H7 v2(49.42,27.52) ; U2.A8 v2(55.82,28.32)
SDR_AD01: length 32.7
  LY4-SIG w0.102: v2(49.42,28.32) 49.05,28.69 49.05,29.56 49.72,30.23 53.91,30.23 v2(55.02,29.12)
  LY7-SIG w0.102: v2(45.42,22) 45.71,21.72 46.47,21.72 46.71,21.47 46.71,20.46 46.86,20.31 47.05,20.31 47.21,20.48 47.21,22.18 47.11,22.28 46.08,22.28 45.98,22.39 45.98,22.59 46.08,22.69 47.11,22.69 47.21,22.79 47.21,22.99 47.11,23.09 46.63,23.09 46.53,23.2 46.53,23.4 46.63,23.5 47.11,23.5 47.21,23.6 47.21,24.04 47.92,24.74 49.08,24.74 49.23,24.89 49.23,25.1 49.1,25.24 47.93,25.24 47.8,25.36 47.8,25.63 47.92,25.76 48.78,25.76 48.9,25.87 48.9,26.11 48.8,26.2 47.97,26.2 47.86,26.31 47.86,26.48 47.94,26.56 48.74,26.56 48.85,26.66 48.85,26.83 48.73,26.95 48.35,26.95 48.14,27.16 48.14,27.66 48.37,27.9 48.99,27.9 v2(49.42,28.32)
  BOTTOM w0.099: U2.B9 v2(55.02,29.12) ; U2.H8 v2(49.42,28.32) ; v2(45.42,22) 44.94,22.48 44.46,22.48 44.39,22.54 43.92,22.54 U1.R2
SDR_AD02: length 32.6
  LY3-SIG w0.102: v2(48.62,28.32) 48.74,28.45 48.74,28.63 49,28.88 49,29.32 49.2,29.52 52.19,29.52 52.98,28.74 54.6,28.74 v2(55.02,28.32)
  LY7-SIG w0.102: v2(48.62,28.32) 48.04,28.32 47.86,28.14 47.71,28.14 47.45,28.41 47.3,28.41 47.16,28.26 47.16,28.12 47.85,27.43 47.85,27.22 47.75,27.12 47.57,27.12 46.83,27.86 46.68,27.86 46.55,27.73 46.55,27.58 46.85,27.28 46.85,26.56 46.72,26.42 46.32,26.42 46.21,26.32 46.21,26.12 46.32,26.02 46.78,26.02 46.89,25.91 46.89,25.71 46.79,25.61 46.23,25.61 46.13,25.51 46.13,25.31 46.24,25.2 46.78,25.2 46.88,25.1 46.88,24.9 46.78,24.8 46.07,24.8 45.97,24.7 45.97,24.52 46.1,24.39 46.72,24.39 46.82,24.29 46.82,24.09 46.71,23.98 46.38,23.98 46.24,23.84 46.24,23.18 46.1,23.04 45.91,23.04 45.77,23.18 45.77,23.8 45.67,23.9 44.06,23.9 43.78,23.63 43.78,23.14 43.98,22.94 44.82,22.94 44.94,22.82 44.94,22.67 44.81,22.54 43.9,22.54 43.74,22.38 43.74,21.98 44.54,21.18 44.78,21.18 44.97,21.37 44.97,21.69 v2(44.66,22)
  BOTTOM w0.099: U1.R1 44.39,22.27 v2(44.66,22) ; U2.B8 v2(55.02,28.32) ; U2.J8 v2(48.62,28.32)
SDR_AD03: length 33.6
  LY4-SIG w0.102: v2(54.22,29.12) 53.58,29.76 50.21,29.76 49.85,29.4 49.85,28.18 49.61,27.94 49.03,27.94 v2(48.62,27.52)
  LY7-SIG w0.102: v2(45.42,21.29) 47.2,19.51 47.65,19.51 47.89,19.75 47.89,20.42 47.57,20.75 47.57,23.92 48.04,24.39 50.84,24.39 50.98,24.53 50.98,24.68 50.84,24.82 49.83,24.82 49.71,24.94 49.71,25.09 49.85,25.24 51.39,25.24 51.52,25.37 51.52,25.51 51.4,25.64 49.47,25.64 49.33,25.78 49.33,25.92 49.46,26.05 51.5,26.05 51.6,26.16 51.6,26.34 51.44,26.5 49.64,26.5 v2(48.62,27.52)
  BOTTOM w0.099: v2(45.42,21.29) 45.06,21.65 44.51,21.65 44.39,21.77 U1.T1 ; U2.C9 v2(54.22,29.12) ; U2.J7 v2(48.62,27.52)
SDR_AD04: length 32.8
  LY4-SIG w0.102: v2(54.22,28.32) 53.78,27.89 53.78,27.68 53.78,27.06 53.33,26.61 52.78,26.61 49.85,23.68 49.85,23.36 49.63,23.14 49.27,23.14 48.89,23.52 v2(48.62,23.52)
  LY8-SIG w0.102: v2(42.74,25.04) 42.78,25.04 43.07,24.75 45.75,24.75 46.01,24.48 46.01,23.75 46.24,23.52 47.93,23.52 49.15,24.75 53.15,24.75 53.52,25.12 53.52,26.59 53.67,26.75 53.91,26.75 54.15,26.51 54.15,24.76 53.73,24.34 49.43,24.34 v2(48.62,23.52)
  BOTTOM w0.099: U1.K3 43.05,24.77 42.78,25.04 v2(42.74,25.04) ; U2.C8 v2(54.22,28.32) ; U2.J3 v2(48.62,23.52)
SDR_AD05: length 33.3
  LY4-SIG w0.102: v2(48.62,22.72) 48.19,22.72 47.77,23.14 47.77,23.69 50.59,26.51 50.59,29.2 50.65,29.25 50.65,29.28 50.86,29.49 50.89,29.49 50.92,29.53 53.01,29.53 v2(53.42,29.12)
  LY8-SIG w0.102: v2(44.22,24.32) 43.81,24.32 43.67,24.19 43.67,22.86 43.39,22.58 43.39,21.35 43.39,21.35 43.39,21.21 43.54,21.05 43.66,21.05 43.82,21.21 43.82,22.33 43.92,22.43 44.11,22.43 44.23,22.31 44.23,21.48 44.4,21.31 44.73,21.31 45.06,21.64 45.73,21.64 45.81,21.56 45.81,21.01 45.99,20.83 47.03,20.83 47.16,20.97 48.14,20.97 48.25,21.08 48.25,21.29 48.16,21.38 46.75,21.38 46.61,21.52 46.61,21.67 46.73,21.8 47.72,21.8 47.81,21.88 47.81,22.07 47.64,22.23 46.12,22.23 45.96,22.39 45.96,22.56 46.13,22.72 v2(48.62,22.72)
  BOTTOM w0.099: v2(44.22,24.32) 44.16,24.27 U1.L2 ; U2.D9 v2(53.42,29.12) ; U2.J2 v2(48.62,22.72)
SDR_AD06: length 33.3
  LY4-SIG w0.102: v2(53.42,28.32) 52.87,27.78 52.87,27.38 49.42,23.92 v2(49.42,23.52)
  LY8-SIG w0.102: v2(44.84,24.33) 44.13,23.63 44.13,23.04 44.77,22.4 44.91,22.4 45.01,22.5 45.01,23 45.16,23.14 45.76,23.14 45.79,23.11 55.29,23.11 55.41,23.23 55.41,25.97 55.16,26.22 54.85,26.22 54.62,26 54.62,24.26 54.36,24 49.89,24 v2(49.42,23.52)
  BOTTOM w0.099: U2.H3 v2(49.42,23.52) ; U1.M1 44.34,23.97 44.47,23.97 v2(44.84,24.33) ; U2.D8 v2(53.42,28.32)
SDR_AD07: length 32.9
  LY4-SIG w0.102: v2(51.82,29.12) 51.43,28.74 51.43,26.51 49.69,24.78 49.28,24.78 48.24,23.74 48.24,23.23 48.38,23.09 48.8,23.09 49.17,22.72 v2(49.42,22.72)
  LY8-SIG w0.102: v2(49.42,22.72) 49.2,22.72 48.83,22.36 48.39,22.36 48.16,22.14 48.16,21.8 48.86,21.1 48.86,20.82 48.73,20.69 47.8,20.69 47.62,20.5 45.71,20.5 45.44,20.78 44.52,20.78 44.28,20.54 41.62,20.54 41.29,20.87 40.79,20.87 40.58,21.08 40.58,21.54 40.38,21.74 39.78,21.74 39.62,21.89 39.62,22.13 39.46,22.3 38.88,22.3 38.53,21.95 38.24,21.95 38.08,22.1 38.08,23.02 38.81,23.75 41.77,23.75 41.84,23.69 41.84,23.69 42.05,23.48 42.05,23.47 42.23,23.29 v2(43.21,23.29)
  BOTTOM w0.099: U2.E9 v2(51.82,29.12) ; U1.M2 43.22,23.34 43.22,23.3 v2(43.21,23.29) ; U2.H2 v2(49.42,22.72)
SDR_AD08: length 33.7
  LY4-SIG w0.102: v2(51.82,21.92) 51.43,22.31 49.8,22.31 v2(49.42,21.92)
  LY7-SIG w0.102: v2(49.42,21.92) 49.98,21.36 51.83,21.36 52.49,20.7 52.49,20.44 52.39,20.34 52.12,20.34 52.02,20.24 52.02,20.04 52.12,19.94 52.39,19.94 52.49,19.83 52.49,19.63 52.39,19.53 52.12,19.53 52.02,19.43 52.02,19.23 52.12,19.12 52.39,19.12 52.49,19.02 52.49,18.82 52.39,18.72 52.12,18.72 52.02,18.62 52.02,18.41 52.12,18.31 52.39,18.31 52.49,18.21 52.49,18.01 52.39,17.9 52.12,17.9 52.02,17.8 52.02,17.6 52.12,17.5 52.39,17.5 52.49,17.4 52.49,17.19 52.25,16.95 51.86,16.95 51.76,17.05 51.76,17.98 51.53,18.2 51.3,18.2 51.11,18.01 51.11,16.92 50.79,16.6 49.99,16.6 49.89,16.5 49.89,16.2 49.79,16.1 49.59,16.1 49.49,16.2 49.49,16.5 49.39,16.6 49.18,16.6 49.08,16.5 49.08,16.2 48.98,16.1 48.78,16.1 48.67,16.2 48.67,16.5 48.57,16.6 48.37,16.6 48.27,16.5 48.27,16.2 48.17,16.1 47.96,16.1 47.86,16.2 47.86,16.5 47.76,16.6 47.56,16.6 47.45,16.5 47.45,16.2 47.35,16.1 47.15,16.1 47.05,16.2 47.05,16.5 46.95,16.6 46.38,16.6 45.91,17.08 44.55,17.08 44.2,17.42 44.2,19.06 43.91,19.36 42.51,19.36 v2(42.14,18.99)
  BOTTOM w0.099: v2(42.14,18.99) U1.V5 ; U2.H1 v2(49.42,21.92) ; U2.E1 v2(51.82,21.92)
SDR_AD09: length 33
  LY4-SIG w0.102: v2(50.22,23.52) 50.71,24.02 52.12,24.02 v2(53.42,22.72)
  LY7-SIG w0.102: v2(50.22,23.52) 49.81,23.12 48.41,23.12 48.19,22.9 48.19,21.3 48.94,20.56 51.08,20.56 51.28,20.36 51.28,20.13 51.12,19.97 49.99,19.97 49.89,19.87 49.89,19.69 50.01,19.57 51.12,19.57 51.22,19.47 51.22,19.26 51.03,19.07 49.19,19.07 49.06,18.95 49.06,18.65 49.17,18.54 49.75,18.54 49.91,18.38 49.91,18.22 49.74,18.05 46.53,18.05 45.35,19.22 45.35,20.3 45.19,20.47 44.12,20.47 43.1,21.48 42.7,21.48 42.55,21.34 41.89,21.34 41.57,21.66 40.66,21.66 40.53,21.79 40.53,22.09 v2(41.14,22.7)
  BOTTOM w0.099: U2.G3 v2(50.22,23.52) ; U1.R7 v2(41.14,22.7) ; U2.D2 v2(53.42,22.72)
SDR_AD10: length 33.4
  LY3-SIG w0.102: v2(49.42,29.12) 49.42,28.82 49.29,28.69 49.26,28.69 49.05,28.48 49.05,28.45 49.03,28.43 49.03,26.42 51.16,24.29 51.91,24.29 52.5,23.7 52.5,22.84 v2(53.42,21.92)
  LY7-SIG w0.102: v2(37.2,22.35) 37.9,21.65 38.39,21.65 38.49,21.75 38.49,22.04 38.78,22.33 39.33,22.33 39.57,22.09 39.57,21.79 39.7,21.67 39.97,21.67 40.13,21.83 40.13,22.07 39.67,22.54 39.67,23.42 40.04,23.79 41.74,23.79 42.05,23.48 42.05,23.48 42.15,23.37 42.61,23.37 42.93,23.69 43.28,23.69 43.57,23.97 43.57,25.62 43.72,25.76 43.87,25.76 44,25.62 44,24.89 44.11,24.79 44.28,24.79 44.4,24.91 44.4,25.65 44.56,25.81 45.25,25.81 46.22,26.78 46.22,28.07 46.85,28.7 49,28.7 v2(49.42,29.12)
  BOTTOM w0.099: U1.T14 37.64,22.04 37.33,22.35 v2(37.2,22.35) ; U2.D1 v2(53.42,21.92) ; U2.H9 v2(49.42,29.12)
SDR_AD11: length 33.1
  LY4-SIG w0.102: v2(50.22,22.72) 50.6,23.11 51.54,23.11 52.32,22.33 53.82,22.33 v2(54.22,22.72)
  LY8-SIG w0.102: v2(50.22,22.72) 50.03,22.72 49.66,22.35 49.28,22.35 49.02,22.1 49.02,21.69 49.9,20.81 49.9,20.51 49.74,20.35 47.93,20.35 47.78,20.2 47.78,19.91 47.64,19.77 46.94,19.77 46.6,20.11 45.5,20.11 45.19,20.42 44.67,20.42 44.48,20.22 41.27,20.22 40.87,20.62 40.47,20.62 40.19,20.34 39.99,20.34 39.87,20.46 39.87,20.85 39.76,20.96 39.52,20.96 39.42,20.86 39.42,19.78 39.32,19.68 39.13,19.68 39.02,19.78 39.02,20.75 38.91,20.86 38.68,20.86 38.57,20.75 38.57,20.27 38.45,20.15 38.3,20.15 38.16,20.29 38.16,20.68 37.82,21.02 36.5,21.02 36.27,20.79 35.44,20.79 35.2,21.03 35.2,21.64 v2(37.27,23.71)
  BOTTOM w0.099: U2.C2 v2(54.22,22.72) ; U2.G2 v2(50.22,22.72) ; v2(37.27,23.71) 37.24,23.71 37.14,23.61 U1.N15
SDR_AD12: length 32.4
  LY4-SIG w0.102: v2(54.22,21.92) 53.75,21.46 50.68,21.46 v2(50.22,21.92)
  LY8-SIG w0.102: v2(50.22,21.92) 50.22,21.57 50.6,21.18 50.87,21.18 51.28,21.59 51.52,21.59 51.63,21.48 51.63,21.15 49.49,19 44.95,19 44.28,18.34 43.55,18.34 43.06,18.83 42.63,18.83 42.27,18.47 36.29,18.47 34.13,20.63 34.13,21.85 35.07,22.8 35.07,23.31 v2(34.57,23.81)
  BOTTOM w0.099: U1.L19 35.02,24.27 v2(34.57,23.81) ; U2.C1 v2(54.22,21.92) ; U2.G1 v2(50.22,21.92)
SDR_AD13: length 33.6
  LY3-SIG w0.102: v2(55.02,22.72) 54.63,23.11 54.63,23.75 52.8,25.58 51.16,25.58 50.22,26.53 v2(50.22,27.52)
  LY8-SIG w0.102: v2(50.22,27.52) 49.41,26.72 48.02,26.72 47.66,27.08 47.11,27.08 46.38,26.34 45.61,26.34 45.38,26.11 43.99,26.11 43.47,26.63 42.66,26.63 42.44,26.41 42,26.41 41.77,26.64 41.35,26.64 41.19,26.47 40.98,26.47 40.97,26.47 40.97,26.47 40.76,26.26 40.76,26.25 40.34,25.83 40.01,25.83 39.14,26.7 38.69,26.7 38.46,26.47 37.92,26.47 37.79,26.34 36.6,26.34 36.15,26.8 34.83,26.8 34.26,26.23 34.26,25.78 35.04,25 35.04,24.34 34.91,24.21 34.12,24.21 33.81,23.9 v2(33.81,23.56)
  BOTTOM w0.099: U2.B2 v2(55.02,22.72) ; U2.G7 v2(50.22,27.52) ; U1.L18 34.83,23.46 33.91,23.46 v2(33.81,23.56)
SDR_AD14: length 34.4
  LY3-SIG w0.102: v2(55.02,21.92) 55.41,22.32 55.41,24.36 53.35,26.43 51.03,26.43 50.58,26.87 50.58,27.68 50.22,28.04 v2(50.22,28.32)
  LY8-SIG w0.102: v2(34.59,24.6) 34.28,24.91 33.55,24.91 33.25,25.22 33.25,27.17 34.52,28.44 36.15,28.44 36.36,28.65 40.29,28.65 41.03,27.91 41.33,27.91 41.45,28.03 42.28,28.03 42.53,27.78 42.53,27.59 42.75,27.37 45.3,27.37 46.62,28.69 49.85,28.69 v2(50.22,28.32)
  BOTTOM w0.099: U2.B1 v2(55.02,21.92) ; U2.G8 v2(50.22,28.32) ; v2(34.59,24.6) 34.72,24.6 34.89,24.77 U1.K19
SDR_AD15: length 32.8
  LY8-SIG w0.102: v2(33.86,24.5) 33.35,23.99 33.35,20.53 35.78,18.1 42.61,18.1 42.76,17.96 48.92,17.96 52.38,21.43 55.2,21.43 55.45,21.68 55.45,22.36 v2(55.82,22.72)
  BOTTOM w0.099: U2.A2 v2(55.82,22.72) ; v2(33.86,24.5) 34.4,25.04 35.36,25.04 U1.K18
SDR_CASZ: length 32.5
  LY8-SIG w0.102: v2(36.1,26.26) 35.28,26.26 35.11,26.09 35.11,25.95 35.29,25.77 36.74,25.77 36.84,25.66 36.84,25.19 37.36,24.68 38.22,24.68 38.35,24.55 38.35,24.18 38.45,24.08 38.65,24.08 38.75,24.18 38.75,24.99 38.86,25.1 39.03,25.1 39.16,24.97 39.16,24.18 39.26,24.08 39.47,24.08 39.57,24.18 39.57,24.99 39.67,25.1 39.85,25.1 39.97,24.97 39.97,24.18 40.08,24.08 40.28,24.08 40.38,24.18 40.38,24.55 40.48,24.65 41.94,24.65 42.38,25.1 42.38,25.19 42.85,25.66 44.96,25.66 45.16,25.46 45.67,25.46 45.82,25.3 46.81,25.3 46.89,25.23 46.89,24.94 46.76,24.82 46.46,24.82 46.38,24.74 46.38,24 46.49,23.89 47.62,23.89 48.94,25.21 52.8,25.21 53.03,25.45 53.03,26.69 52.62,27.11 51.43,27.11 v2(51.02,27.52)
  BOTTOM w0.099: U1.G18 v2(36.1,26.26) ; U2.F7 v2(51.02,27.52)
SDR_CKE: length 32.6
  LY7-SIG w0.102: v2(51.02,23.52) 51.63,24.14 52.15,24.14 52.27,24.02 52.27,22.23 52.42,22.08 52.57,22.08 52.74,22.25 52.74,31.07 52.14,31.67 51.48,31.67 50.18,32.98 46.77,32.98 44.93,31.13 44.93,29.48 44.72,29.27 43.68,29.27 43.54,29.42 41.15,29.42 40.59,29.97 39.95,29.97 v2(39.38,30.54)
  BOTTOM w0.099: v2(39.38,30.54) 39.92,30 39.92,29.04 U1.B10 ; U2.F3 v2(51.02,23.52)
SDR_CLK: length 32.7
  LY7-SIG w0.102: v2(36.14,19.62) 35.39,19.62 35.1,19.9 35.1,20.17 35.32,20.39 36.15,20.39 36.7,19.84 37.49,19.84 37.93,20.27 39.94,20.27 40.29,20.62 41.68,20.62 42.18,20.12 44.31,20.12 44.8,19.63 44.8,18.25 44.96,18.09 45.78,18.09 46.81,17.07 49.15,17.07 49.27,17.19 49.27,17.56 49.41,17.7 49.62,17.7 49.73,17.6 49.73,17.36 50.02,17.07 50.51,17.07 50.72,17.28 50.72,18.34 50.97,18.59 51.48,18.59 51.71,18.82 51.71,20.49 51.29,20.92 49.34,20.92 49.02,21.23 49.02,22.1 49.26,22.34 50.63,22.34 v2(51.02,22.72)
  BOTTOM w0.099: U1.V17 v2(36.14,19.62) ; U2.F2 v2(51.02,22.72)
SDR_CSZ: length 32.6
  LY7-SIG w0.102: v2(39.55,29.84) 39.85,29.54 40.58,29.54 40.91,29.21 43.37,29.21 43.62,28.96 44.91,28.96 45.44,29.48 46.61,29.48 46.73,29.61 46.73,29.84 46.55,30.03 45.68,30.03 45.4,30.31 45.4,30.98 46.36,31.94 46.5,31.94 46.71,31.74 46.85,31.74 46.99,31.88 46.99,32.03 46.79,32.23 46.79,32.37 46.94,32.52 47.29,32.52 47.39,32.41 47.39,30.94 47.5,30.84 47.69,30.84 47.8,30.94 47.8,32.41 47.9,32.52 48.1,32.52 48.2,32.41 48.2,31.79 48.3,31.68 48.51,31.68 48.61,31.79 48.61,32.41 48.71,32.52 48.91,32.52 49.01,32.41 49.01,31.79 49.12,31.68 49.32,31.68 49.42,31.79 49.42,32.41 49.52,32.52 50.06,32.52 51.06,31.52 51.06,30.8 50.67,30.41 47.9,30.41 47.77,30.28 47.77,30.08 47.87,29.98 49.99,29.98 50.22,29.75 v2(50.22,29.12)
  BOTTOM w0.099: U2.G9 v2(50.22,29.12) ; v2(39.55,29.84) 39.55,29.67 U1.A11
SDR_LDQM: length 32.9
  LY8-SIG w0.102: v2(37.59,25.97) 37.85,25.7 39.4,25.7 39.72,25.39 40.41,25.39 40.94,24.85 41.83,24.85 42.04,25.06 42.04,25.14 42.76,25.86 45.43,25.86 45.7,26.14 47.79,26.14 47.87,26.06 47.87,25.54 48,25.41 48.21,25.41 48.31,25.51 48.31,26.13 48.41,26.23 48.61,26.23 48.72,26.13 48.72,25.74 48.82,25.64 49.02,25.64 49.12,25.74 49.12,26.13 49.22,26.23 49.43,26.23 49.53,26.13 49.53,25.74 49.63,25.64 49.83,25.64 49.93,25.74 49.93,26.58 50.04,26.68 50.21,26.68 50.34,26.55 50.34,25.74 50.44,25.64 50.65,25.64 50.75,25.74 50.75,26.21 50.85,26.31 51.05,26.31 51.15,26.21 51.15,25.74 51.26,25.64 51.46,25.64 51.56,25.74 51.56,26.13 51.66,26.23 51.87,26.23 51.97,26.13 51.97,25.74 52.07,25.64 52.43,25.64 52.6,25.81 52.6,26.49 52.39,26.7 51.15,26.7 50.65,27.2 50.65,27.68 50.93,27.96 51.95,27.96 52.28,27.62 52.84,27.62 53,27.79 53,28.79 52.83,28.97 52.46,28.97 v2(51.82,28.32)
  BOTTOM w0.099: U1.G16 36.93,25.97 37.58,25.97 v2(37.59,25.97) ; U2.E8 v2(51.82,28.32)
SDR_RASZ: length 32.8
  LY8-SIG w0.102: v2(33.86,25.26) 33.46,25.66 33.46,26.17 33.7,26.41 34.07,26.41 34.84,27.18 36.65,27.18 36.94,27.48 37.31,27.48 37.43,27.59 39.28,27.59 39.5,27.38 40.32,27.38 40.43,27.49 40.56,27.62 41.01,27.62 41.16,27.47 41.16,27.25 41.5,26.9 41.74,26.9 42.03,27.19 42.4,27.19 42.6,27 45.39,27 45.58,26.81 46.02,26.81 47.14,27.94 50.45,27.94 50.62,28.11 50.62,29.52 51.25,30.14 54.24,30.14 54.4,29.98 54.4,29.74 54.29,29.62 51.57,29.62 51.39,29.44 51.39,28.7 v2(51.02,28.32)
  BOTTOM w0.099: v2(33.86,25.26) U1.J18 ; U2.F8 v2(51.02,28.32)
SDR_UDQM: length 33.4
  LY8-SIG w0.102: v2(34.62,26.03) 35.57,25.08 35.57,22.63 34.72,21.77 34.72,20.76 35.47,20.01 36.16,20.01 36.29,20.14 36.29,20.47 36.39,20.57 36.61,20.57 36.72,20.46 36.72,18.99 36.87,18.84 37.51,18.84 37.61,18.94 37.61,19.09 37.27,19.43 37.27,20.56 37.37,20.66 37.6,20.66 37.73,20.53 37.73,19.59 37.96,19.36 49.31,19.36 50.45,20.5 50.45,20.84 49.78,21.51 49.78,22.1 50.03,22.35 51.38,22.35 51.47,22.25 51.47,22.11 51.29,21.92 v2(51.02,21.92)
  BOTTOM w0.099: U2.F1 v2(51.02,21.92) ; U1.H19 34.89,25.76 v2(34.62,26.03)
SDR_WEZ: length 33.1
  LY7-SIG w0.102: v2(36.6,28.26) 37.54,29.2 40.52,29.2 40.81,28.91 43.13,28.91 43.49,28.55 43.49,28.41 43.49,28.41 43.49,28.12 43.49,28.12 43.49,26.84 43.35,26.71 43.07,26.71 42.98,26.79 42.98,27.08 42.89,27.18 42.68,27.18 42.55,27.05 42.55,25.9 42.71,25.74 43.17,25.74 43.59,26.16 44.09,26.16 44.28,26.35 44.28,26.9 44.18,27 43.89,27 43.79,27.1 43.79,27.3 43.89,27.41 44.43,27.41 44.85,26.99 45.15,26.99 45.25,27.09 45.25,27.34 44.77,27.81 43.89,27.81 43.79,27.91 43.79,28.12 43.89,28.22 44.18,28.22 44.28,28.32 44.28,28.52 44.48,28.72 44.9,28.72 45.61,28.02 45.84,28.02 45.94,28.12 45.94,28.88 46.07,29 47.85,29 48.47,29.63 49.56,29.63 49.8,29.39 49.8,28.84 49.93,28.72 51.32,28.72 51.43,28.83 51.43,29.8 51.3,29.93 50.84,29.93 50.73,29.82 50.73,29.41 v2(51.02,29.12)
  BOTTOM w0.099: U1.B17 36.14,28.72 v2(36.6,28.26) ; U2.F9 v2(51.02,29.12)
SSI0CLK_U4RX: length 15.2
  LY3-SIG w0.102: v2(42.02,22.14) 41.77,21.9 41.77,20.95 41.62,20.8 40.46,20.8 40.31,20.65 40.31,18.59 39.75,18.03 39.75,15.24 40.39,14.61 40.39,13.84 41.54,12.69 v1(41.54,11.11)
  BOTTOM w0.099: J3.3 v1(41.54,11.11) ; U1.T6 v2(42.02,22.14)
SSI0FSS_U4TX: length 15.6
  LY4-SIG w0.102: v2(42.97,21.87) 43.05,21.87 43.54,21.38 43.54,21.36 43.56,21.34 43.56,21.04 43.56,21.04 43.56,21.03 43.35,20.82 43.3,20.82 42.55,20.07 42.55,19.57 42.79,19.33 42.79,18.75 42.55,18.5 42.55,17.53 40.83,15.81 v1(40.83,10.4)
  BOTTOM w0.099: J3.4 v1(40.83,10.4) ; v2(42.97,21.87) 42.98,21.86 42.98,21.73 42.51,21.27 U1.U5
SSI0XDAT0: length 14.5
  LY4-SIG w0.102: v2(42.9,18.32) 42.9,17.16 42.06,16.32 42.06,13.48 41.15,12.57 41.15,10.79 41.4,10.54 41.4,10.29 40.81,9.7 v1(40.12,9.7)
  BOTTOM w0.099: U1.V4 42.36,20.49 42.36,19.53 42.9,18.99 v2(42.9,18.32) ; J3.5 v1(40.12,9.7)
SSI0XDAT1: length 15.3
  LY4-SIG w0.102: v1(39.41,8.99) 40.74,8.99 42.04,10.29 42.04,11.15 41.91,11.27 41.91,12.45 42.65,13.19 42.65,16.32 43.31,16.97 43.31,19.34 v2(42.9,19.75)
  BOTTOM w0.099: U1.W4 42.64,20.01 v2(42.9,19.75) ; J3.6 v1(39.41,8.99)
SW_ON/OFF: length 44.5
  TOP w0.099: C27.1 R28.1 57.92,20.04 SW2.1 56.54,19.32 56.54,19.54 v1(57,20) ; v1(36.59,6.16) 36.59,8.01 37.34,8.76 37.34,19.08 35.79,20.63 35.79,20.91 v2(36.15,21.27) 36.63,20.79 42.73,20.79 42.74,20.77 43.04,20.77 43.05,20.79 45.08,20.79 45.74,20.13 46.85,20.13 48,21.27 53.79,21.27 v1(54.06,21)
  BOTTOM w0.099: v1(54.06,21) 55.06,20 v1(57,20) ; U1.U18 v2(36.15,21.27) ; J3.10 v1(36.59,6.16)
SW_SCAN: length 31.9
  TOP w0.099: v1(58.77,34.05) 58.78,34.05 58.89,34.05 59.56,33.38 SW1.1 60.04,33.4 R27.1 C26.1 ; v1(56.95,33.42) 56.6,33.06 56.6,30.46 55.86,29.72 48.57,29.72 48.01,29.15 48.01,23.95 46.47,22.41 43.38,22.41 42.62,23.17 42.62,24.01 42.45,24.17 v2(42.45,24.35)
  BOTTOM w0.099: v2(42.45,24.35) 42.53,24.28 42.53,24.12 42.64,24.01 U1.M4 ; v1(58.77,34.05) 58.14,33.42 v1(56.95,33.42)
SYNCZ: length 41.1
  LY7-SIG w0.102: v1(28.95,37.38) 30.51,38.93 45.32,38.93 v1(46.25,38)
  BOTTOM w0.099: U1.U2 43.66,21.25 44.33,21.25 44.34,21.24 44.54,21.24 45.27,20.51 46.25,20.51 46.69,20.95 46.69,29.13 45.73,30.09 45.73,32.27 46.48,33.02 46.48,37.77 v1(46.25,38) ; J2.4 v1(28.95,37.38)
SYS_PWR: length 16.7
  TOP w0.203: 20.73,18.29 20.77,18.33 U11.A1 21.35,18.02 21.11,17.78 20.73,17.78 20.47,18.03
  TOP w0.254: C84.1 v1(45.85,34.8) 45.72,34.67 U18.5 ; C81.1 v1(35.18,34.8) 35.05,34.67 U15.5 ; U16.5 38.61,34.67 v1(38.74,34.8) C82.1 ; U18.2 v1(46.37,30.73) ; C83.1 v1(42.3,34.8) 42.17,34.67 U17.5 ; R53.1 v1(44.92,34.83)
  BOTTOM w0.254: 32.92,8.51 32.89,8.54 U12.A3 ; 33.43,8.89 33.48,8.94 U12.A2 33.89,9.31 33.81,9.4 ; 33.43,8.51 33.68,8.51 33.89,8.3 U12.B2 33.44,8.14 ; C58.1 v1(45.83,40.06) ; U12.A3 32.89,9.37 32.92,9.4 ; U12.A3 32.34,8.94 32.28,8.89 ; C59.1 v1(45.83,42.61)
  vias: v1(19.94,22.23) v1(20.32,21.59) v1(20.83,22.23) v1(21.21,21.59) v1(28.09,9.65) v1(28.73,9.65) v1(29.36,9.65)
TDRDYZ: length 11.4
  BOTTOM w0.099: J2.14 38.95,37.31 38.99,37.27 38.99,37.24 39.04,37.18 39.04,36.86 38.95,36.77 38.95,35.36 39.15,35.16 39.15,31.66 39.6,31.21 40.23,31.21 40.63,30.81 40.63,30.27 40.36,30 40.36,29.04 U1.B8
TIVA_DATAEN_MASK: length 14.2
  LY4-SIG w0.102: v2(42.02,25.63) 42.78,26.4 42.78,26.4 42.99,26.61 43,26.61 44.07,27.68 44.07,28.32 45.85,30.1 45.85,32 v1(48.13,34.29)
  BOTTOM w0.099: U1.H3 43.07,25.76 42.79,25.49 42.31,25.49 42.17,25.63 v2(42.02,25.63) ; v1(48.13,34.29) 48.49,34.65 49.14,34.65 49.32,34.83 U9.2
